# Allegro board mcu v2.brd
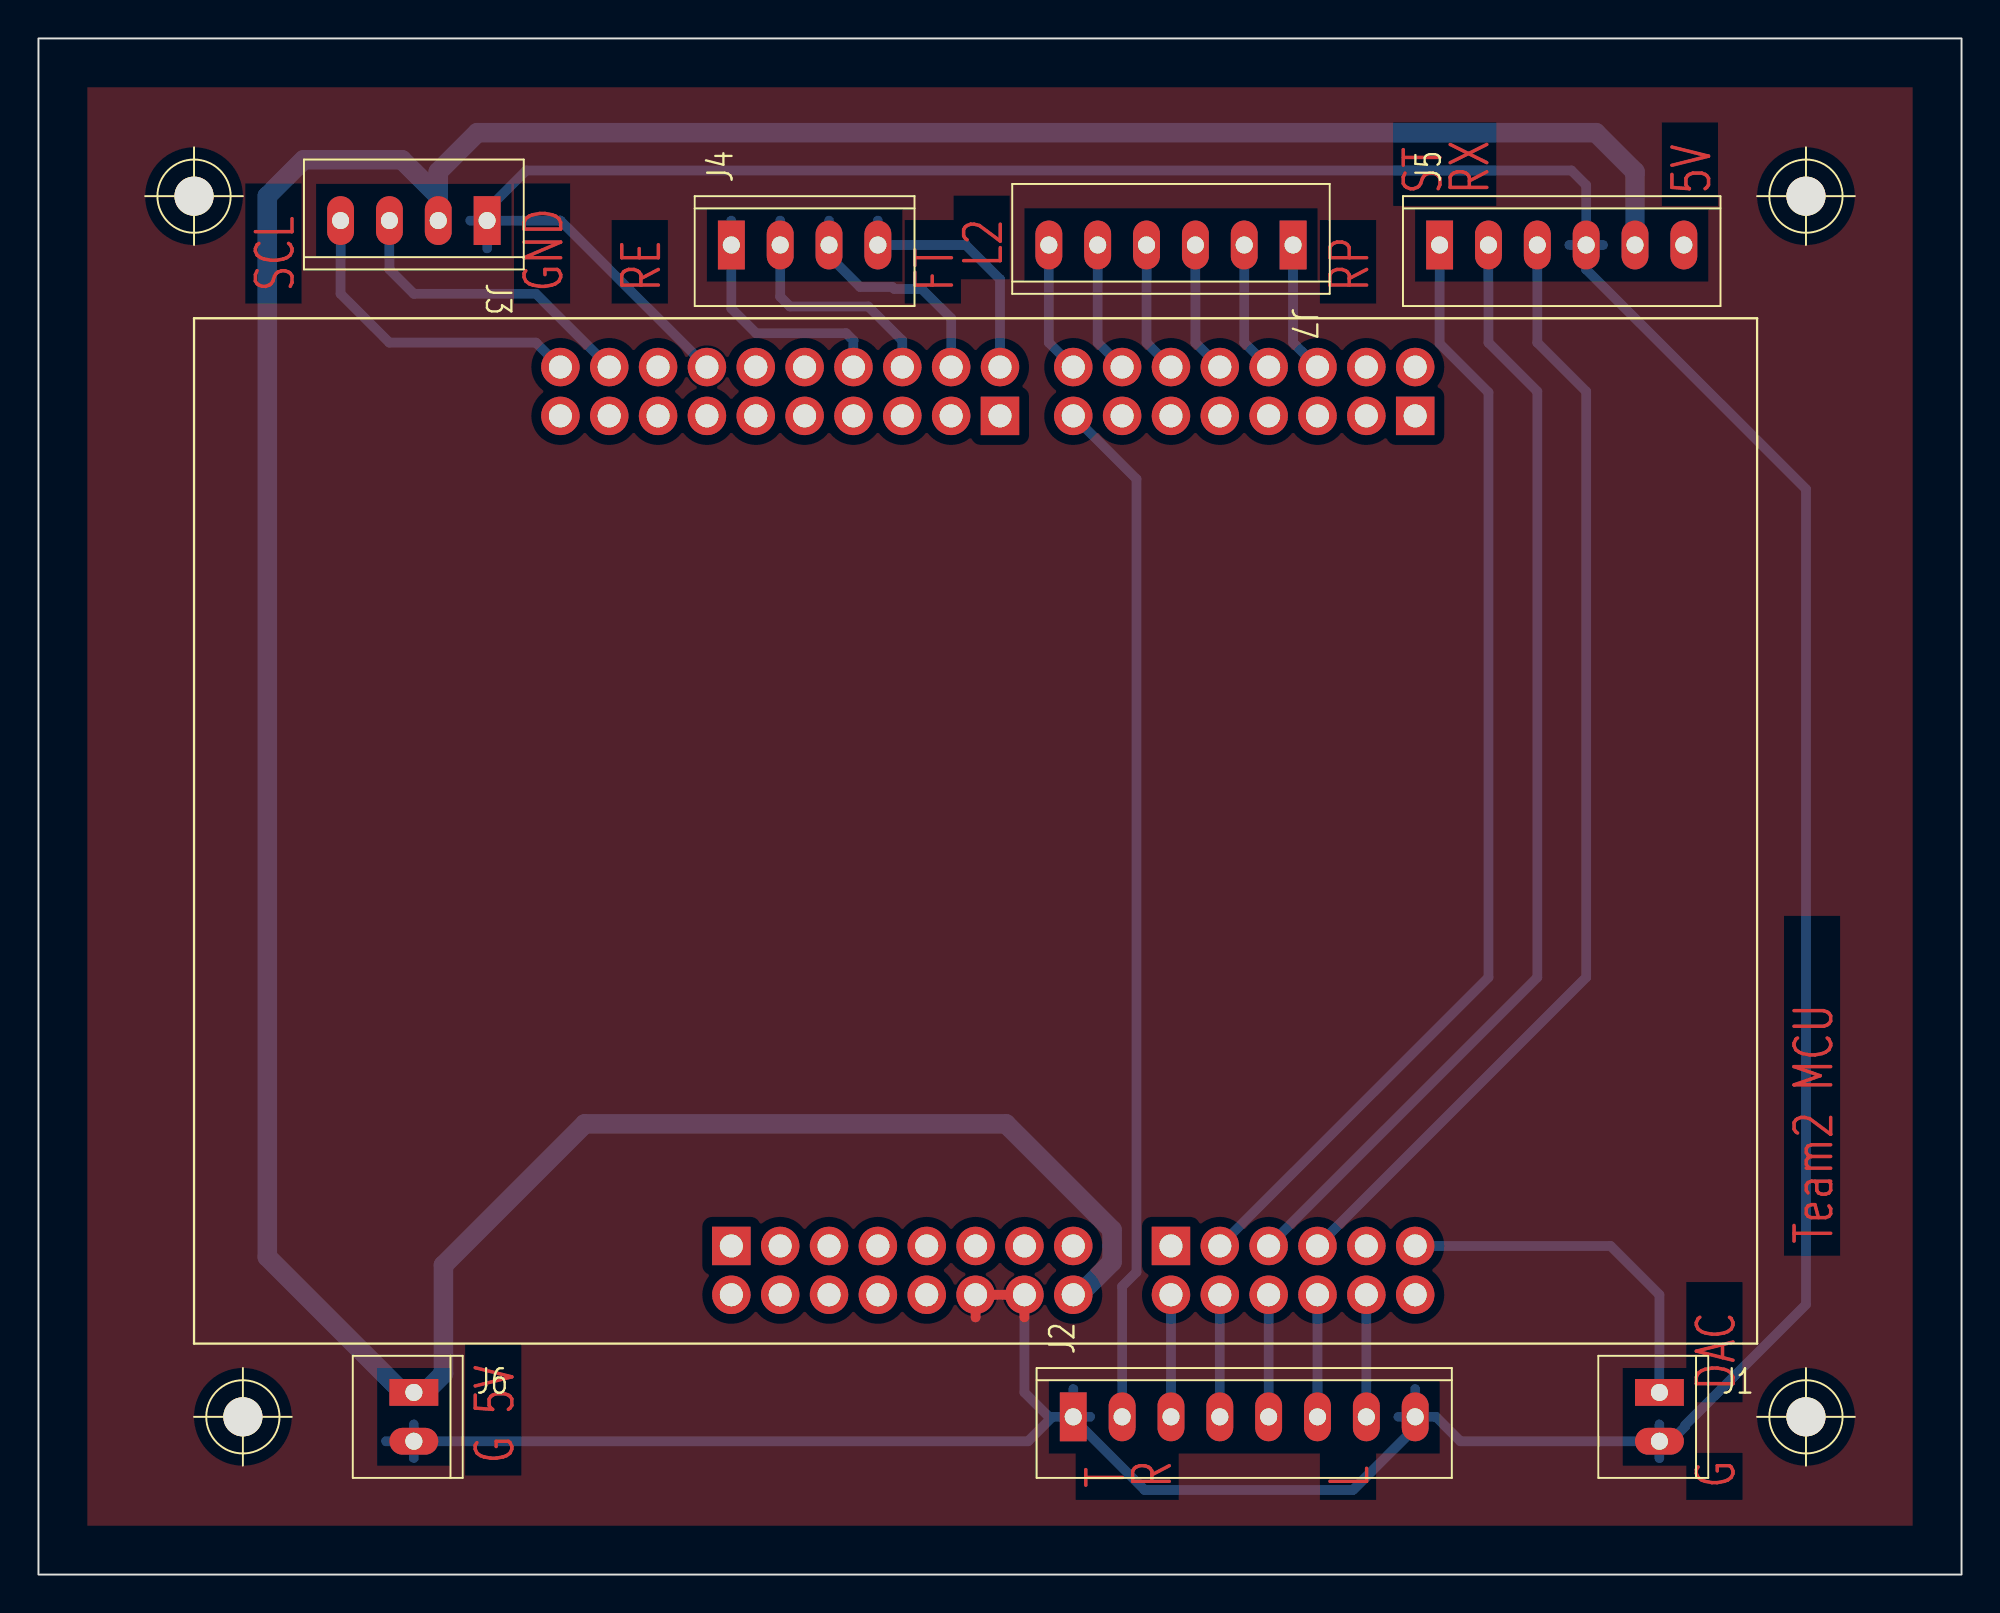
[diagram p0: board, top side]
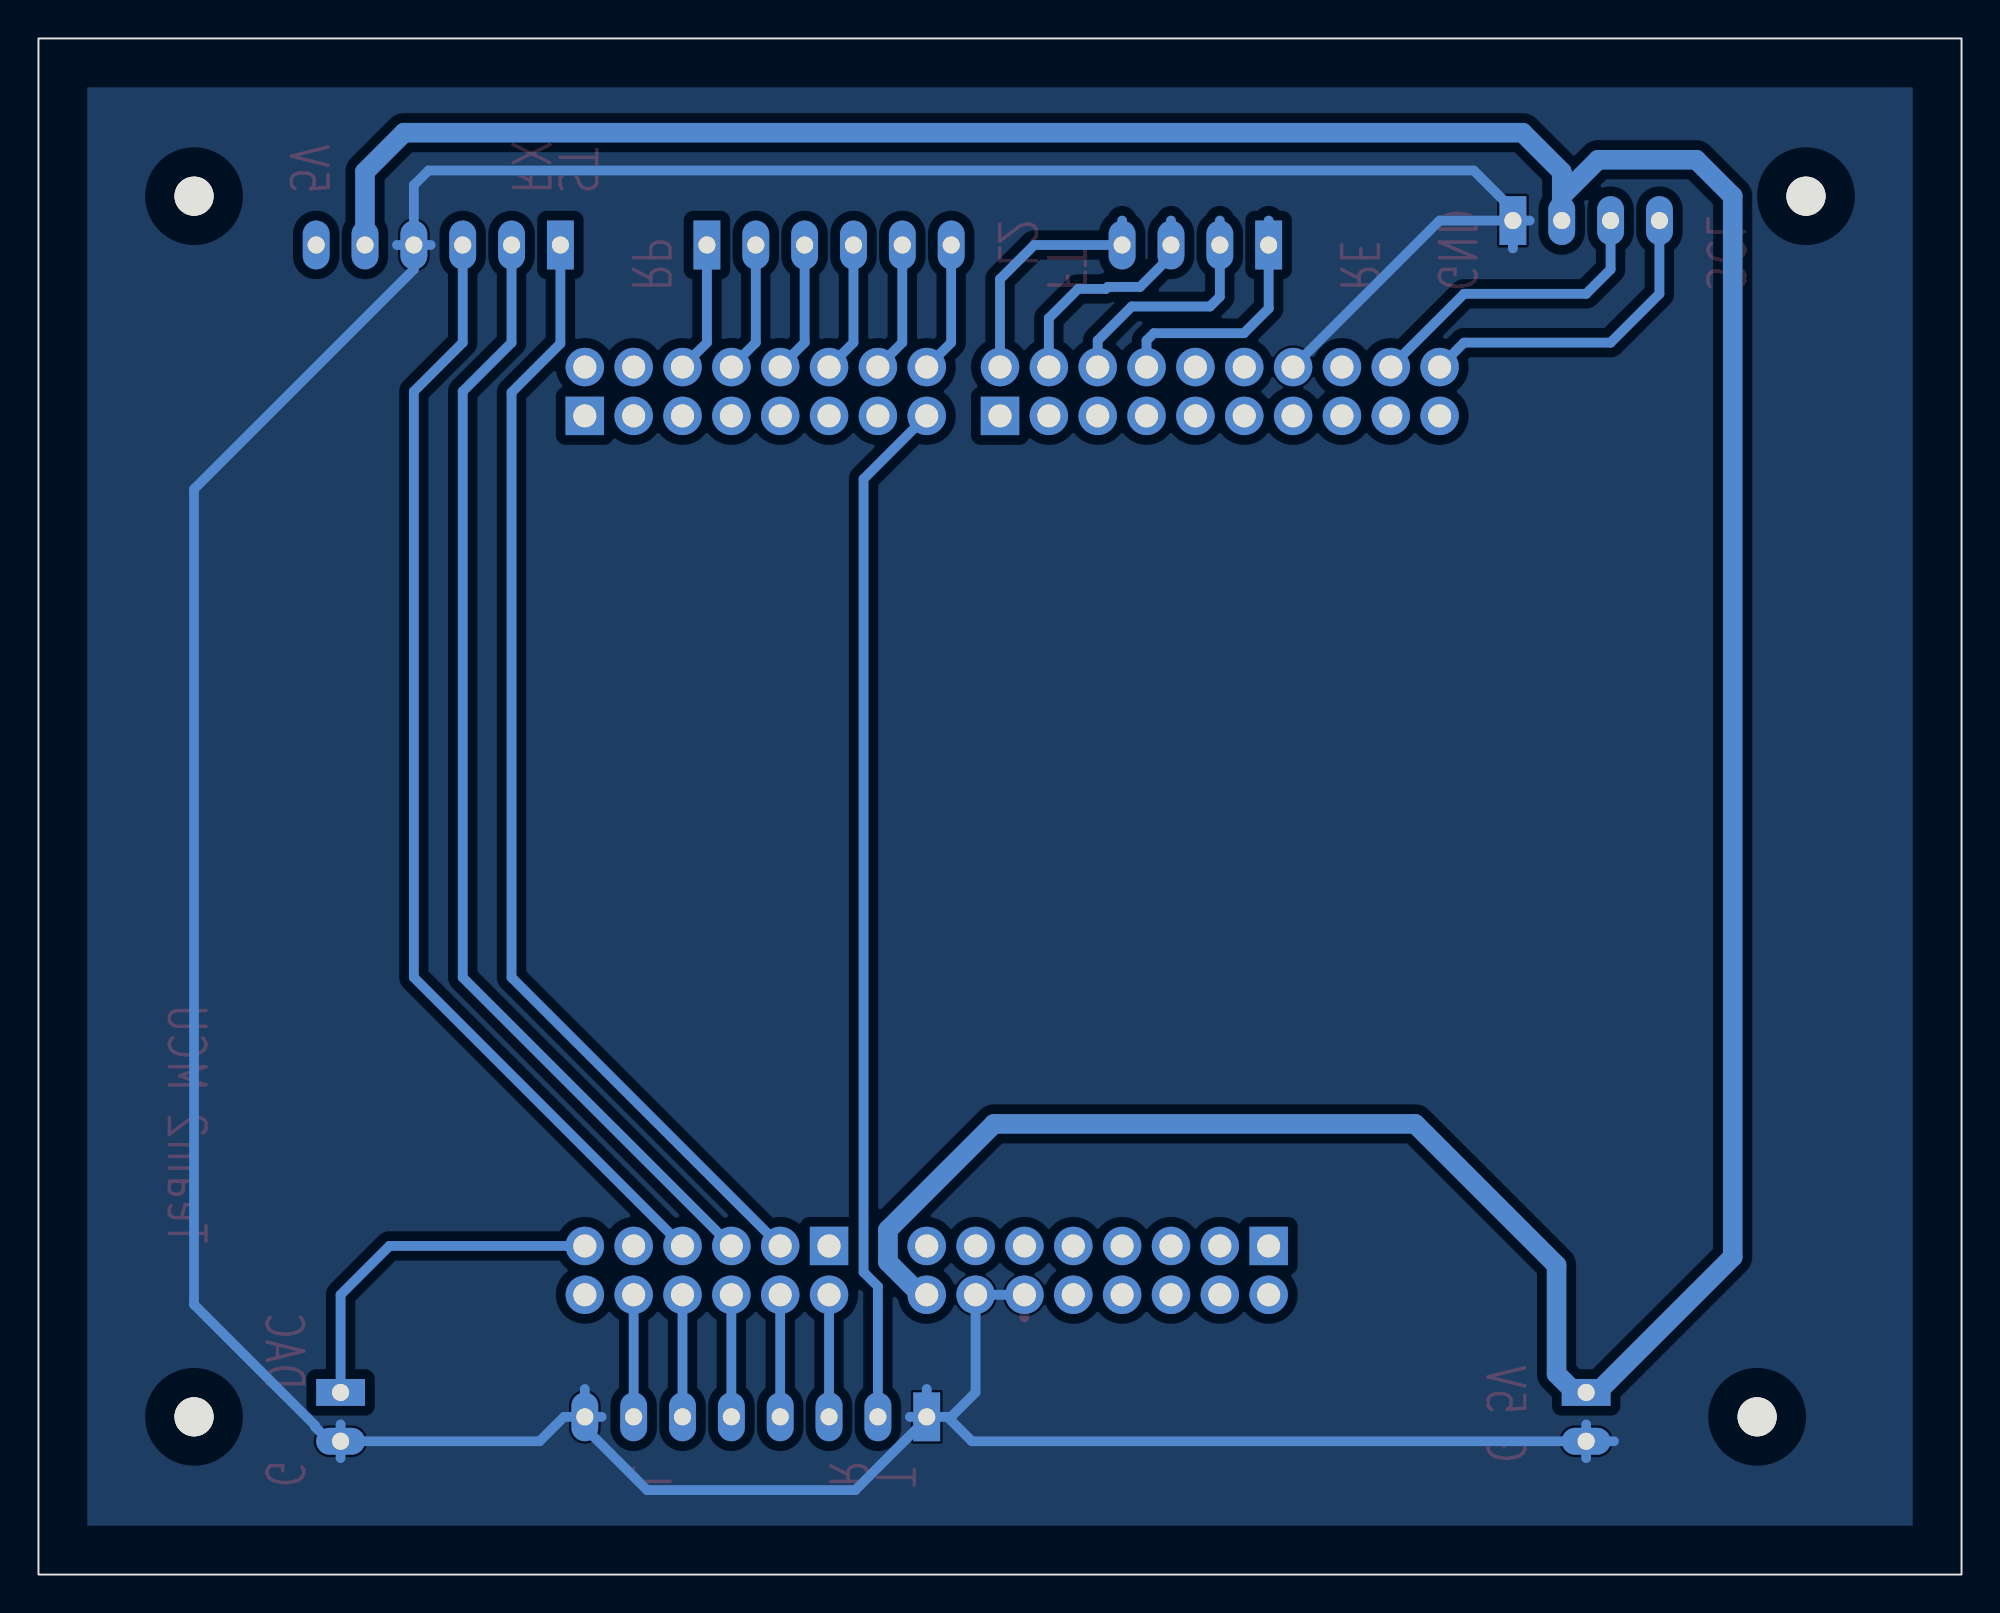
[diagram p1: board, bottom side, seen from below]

Outline 100 x 79.91 mm; copper layers: TOP, BOTTOM. Coordinates in mm from the lower left corner of the outline.
Outline path: rectangle 0,0 100,79.91

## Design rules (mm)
constraint set DEFAULT: min track width 0.508

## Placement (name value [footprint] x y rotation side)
J1  DAC  [GU-MOLEX2]  84.29 9.47 0 top
J2  Line following  [GU-MOLEX8]  53.81 8.2 90 top
J3  Color sensing  [GU-MOLEX4]  23.33 70.43 270 top
J4  Ultrasonic  [GU-MOLEX4]  36.03 69.16 90 top
J5  Bluetooth  [GU-MOLEX6]  72.86 69.16 90 top
J6  Power  [GU-MOLEX2]  19.52 9.47 0 top
J7  Motor driver  [GU-MOLEX6]  65.24 69.16 270 top
NOREF  -  [unnamed]  8.09 71.7 0 top
NOREF#2  -  [unnamed]  91.91 71.7 0 top
NOREF#3  -  [unnamed]  91.91 8.2 0 top
NOREF#4  -  [unnamed]  10.63 8.2 0 top
U1  FDRM-KL25Z DUAL  [GU-FRDM-KL25Z]  8.09 12.01 0 top

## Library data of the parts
J1 J6 = CON2
J2 = CON8
J3 J4 = CON4
J5 J7 = CON6
U1 = FDRM-KL25Z DUAL

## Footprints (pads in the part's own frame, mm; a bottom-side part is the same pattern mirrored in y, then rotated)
GU-FRDM-KL25Z
  rect 2x2 hole 1.2: J101(63.5,48.26) J201(41.91,48.26) J901(27.94,5.08) J1001(50.8,5.08)
  round 2 hole 1.2: J102(63.5,50.8) J103(60.96,48.26) J104(60.96,50.8) J105(58.42,48.26) J106(58.42,50.8) J107(55.88,48.26) J108(55.88,50.8) J109(53.34,48.26) J110(53.34,50.8) J111(50.8,48.26) J112(50.8,50.8) J113(48.26,48.26) J114(48.26,50.8) J115(45.72,48.26) J116(45.72,50.8) J202(41.91,50.8) J203(39.37,48.26) J204(39.37,50.8) J205(36.83,48.26) J206(36.83,50.8) J207(34.29,48.26) J208(34.29,50.8) J209(31.75,48.26) J210(31.75,50.8) J211(29.21,48.26) J212(29.21,50.8) J213(26.67,48.26) J214(26.67,50.8) J215(24.13,48.26) J216(24.13,50.8) J217(21.59,48.26) J218(21.59,50.8) J219(19.05,48.26) J220(19.05,50.8) J902(27.94,2.54) J903(30.48,5.08) J904(30.48,2.54) J905(33.02,5.08) J906(33.02,2.54) J907(35.56,5.08) J908(35.56,2.54) J909(38.1,5.08) J910(38.1,2.54) J911(40.64,5.08) J912(40.64,2.54) J913(43.18,5.08) J914(43.18,2.54) J915(45.72,5.08) J916(45.72,2.54) J1002(50.8,2.54) J1003(53.34,5.08) J1004(53.34,2.54) J1005(55.88,5.08) J1006(55.88,2.54) J1007(58.42,5.08) J1008(58.42,2.54) J1009(60.96,5.08) J1010(60.96,2.54) J1011(63.5,5.08) J1012(63.5,2.54)
GU-MOLEX2
  rect 2.54x1.397 hole 0.889: 1(0,0)
  oval 2.54x1.397 hole 0.889: 2(0,-2.54)
GU-MOLEX4
  rect 2.54x1.397 hole 0.889: 1(0,0)
  oval 2.54x1.397 hole 0.889: 2(0,-2.54) 3(0,-5.08) 4(0,-7.62)
GU-MOLEX6
  rect 2.54x1.397 hole 0.889: 1(0,0)
  oval 2.54x1.397 hole 0.889: 2(0,-2.54) 3(0,-5.08) 4(0,-7.62) 5(0,-10.16) 6(0,-12.7)
GU-MOLEX8
  rect 2.54x1.397 hole 0.889: 1(0,0)
  oval 2.54x1.397 hole 0.889: 2(0,-2.54) 3(0,-5.08) 4(0,-7.62) 5(0,-10.16) 6(0,-12.7) 7(0,-15.24) 8(0,-17.78)
unnamed
  round 2.032 hole 3.962 unplated: (0,0)

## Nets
5V: J3.2 J5.5 J6.1 U1.J916
GND: J1.2 J2.1 J2.8 J3.1 J5.4 J6.2 U1.J214 U1.J912 U1.J914
P3V3: U1.J904 U1.J908
P5V_USB: U1.J910
BTRX: J5.2 U1.J1005
FRONT-ECHO: J4.3 U1.J204
FRONT-TRIG: J4.4 U1.J202
LEFT1: J2.6 U1.J1008
LEFT2: J2.7 U1.J1010
LEFT-IN-1: J7.5 U1.J114
LEFT-IN-2: J7.6 U1.J116
LEFT-PWM: J7.4 U1.J112
MID: J2.5 U1.J1006
RIGHT1: J2.3 U1.J1002
RIGHT2: J2.4 U1.J1004
RIGHT-ECHO: J4.1 U1.J208
RIGHT-IN-1: J7.2 U1.J108
RIGHT-IN-2: J7.3 U1.J110
RIGHT-PWM: J7.1 U1.J106
RIGHT-TRIG: J4.2 U1.J206
SCL: J3.4 U1.J220
SDA: J3.3 U1.J218
STATE: J5.1 U1.J1003
TRANSISTOR: J2.2 U1.J115
VREFH: U1.J216(VREFH)
N00587: J1.1 U1.J1011
N00956: J5.3 U1.J1007

Pads without a net: J5 6; U1 J101 J102 J103 J104 J105 J107 J109 J111 J113 J201 J203 J205 J207 J209 J210 J211 J212 J213 J215 J217 J219 J901 J902 J903 J905 J906 J907 J909 J911 J913 J915 J1001 J1009 J1012

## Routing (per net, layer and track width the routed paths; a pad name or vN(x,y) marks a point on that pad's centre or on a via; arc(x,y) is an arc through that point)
5V: length 198.5
  BOTTOM w0.508: J3.2 20.79,71.01
  BOTTOM w1.016: U1.J916 54.12,14.55 55.83,16.26 55.83,17.93 50.31,23.44 28.41,23.44 21.06,16.09 21.06,10.44 20.09,9.47 J6.1 18.95,9.47 11.9,16.52 11.9,71.7 13.79,73.6 18.9,73.6 20.79,71.7 ; J5.5 83.02,72.97 80.99,75.01 22.82,75.01 20.79,72.97 20.79,71.7 ; 20.79,71.01 20.79,71.7
GND: length 244.4
  TOP w0.508: 50.09,14.55 U1.J914 51.27,13.38 ; 49.91,14.55 U1.J912 48.73,13.38
  BOTTOM w0.508: J6.2 19.52,7.81 ; J6.2 18.07,6.93 ; J6.2 19.52,6.06 ; J6.2 51.46,6.93 52.73,8.2 ; J1.2 84.86,6.93 85.62,7.7 85.62,7.76 91.91,14.05 91.91,56.46 80.48,67.89 J5.4 ; J1.2 84.29,6.06 ; J1.2 73.94,6.93 72.67,8.2 J2.8 ; J1.2 84.29,7.81 ; J5.4 81.36,69.16 ; J5.4 80.48,72.28 79.72,73.04 25.36,73.04 23.33,71.01 J3.1 ; J5.4 79.6,69.16 ; 52.73,8.2 52.54,8.2 51.27,9.47 U1.J914 U1.J912 ; 52.73,8.2 J2.1 ; J3.1 27.14,70.43 U1.J214 ; J3.1 23.33,68.99 ; J3.1 22.45,70.43 ; J2.8 71.59,7.63 68.35,4.39 57.52,4.39 53.81,8.11 J2.1 ; J2.8 71.59,9.65 ; J2.8 70.71,8.2 ; J2.1 54.69,8.2 ; J2.1 53.81,9.65
BTRX: length 58.9
  BOTTOM w0.508: U1.J1005 77.94,31.06 77.94,61.54 75.4,64.08 J5.2
FRONT-ECHO: length 12.1
  BOTTOM w0.508: 41.11,70.43 J4.3 41.11,68.59 42.72,66.98 44.4,66.98 44.5,66.88 45.94,66.88 47.46,65.35 U1.J204
FRONT-TRIG: length 12.9
  BOTTOM w0.508: 43.65,70.43 J4.4 48.22,69.16 50,67.39 U1.J202
LEFT1: length 6.4
  BOTTOM w0.508: U1.J1008 J2.6
LEFT2: length 6.4
  BOTTOM w0.508: U1.J1010 J2.7
LEFT-IN-1: length 6.9
  BOTTOM w0.508: U1.J114 55.08,64.08 J7.5
LEFT-IN-2: length 6.9
  BOTTOM w0.508: J7.6 52.54,64.08 U1.J116
LEFT-PWM: length 6.9
  BOTTOM w0.508: J7.4 57.62,64.08 U1.J112
MID: length 6.4
  BOTTOM w0.508: U1.J1006 J2.5
RIGHT1: length 6.4
  BOTTOM w0.508: U1.J1002 J2.3
RIGHT2: length 6.4
  BOTTOM w0.508: U1.J1004 J2.4
RIGHT-ECHO: length 13
  BOTTOM w0.508: 36.03,70.43 J4.1 36.03,65.86 37.32,64.58 42,64.58 42.38,64.2 U1.J208
RIGHT-IN-1: length 6.9
  BOTTOM w0.508: U1.J108 62.7,64.08 J7.2
RIGHT-IN-2: length 6.9
  BOTTOM w0.508: J7.3 60.16,64.08 U1.J110
RIGHT-PWM: length 6.9
  BOTTOM w0.508: U1.J106 65.24,64.08 J7.1
RIGHT-TRIG: length 12.6
  BOTTOM w0.508: 38.57,70.43 J4.2 38.57,66.47 39.08,65.97 43.15,65.97 44.92,64.2 U1.J206
SCL: length 16.8
  BOTTOM w0.508: J3.4 15.71,66.62 18.25,64.08 25.87,64.08 U1.J220
SDA: length 16.1
  BOTTOM w0.508: U1.J218 25.87,66.62 19.52,66.62 18.25,67.89 J3.3
STATE: length 58.9
  BOTTOM w0.508: J5.1 72.86,64.04 75.4,61.5 75.4,31.06 U1.J1003
TRANSISTOR: length 53.7
  BOTTOM w0.508: J2.2 56.35,14.99 57.1,15.73 57.1,56.99 U1.J115
N00587: length 18.8
  BOTTOM w0.508: J1.1 84.29,14.55 81.75,17.09 U1.J1011
N00956: length 58.9
  BOTTOM w0.508: J5.3 77.94,64.08 80.48,61.54 80.48,31.06 U1.J1007

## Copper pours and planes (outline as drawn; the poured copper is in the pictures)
GND on TOP, BOTTOM: 2.54,77.37 97.46,77.37 97.46,2.54 2.54,2.54

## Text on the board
TOP: SCL | 5V | G | GND | RE | FT | L2 | T | R | RP | L | ST | RX | DAC | Team2 MCU
